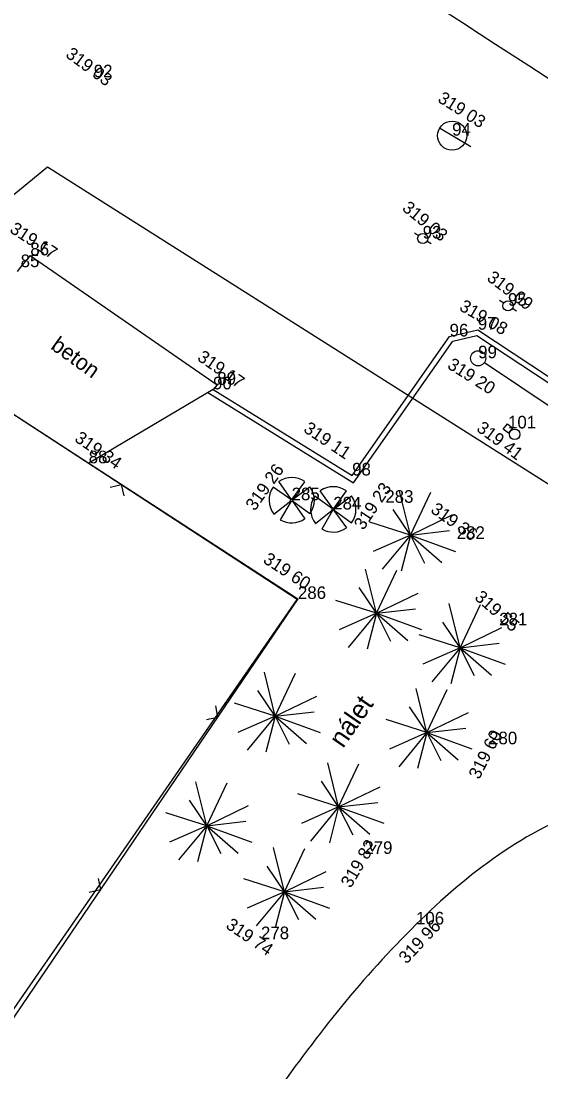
# Model space of a CAD drawing. Extents: x -742884 to -742543, y -1054677 to -1054433.
# Drawn here: x -742659.68 to -742647.31, y -1054548.61 to -1054523.59 of the extents above; entities that cross this region are included whole.
import ezdxf

# ---------------------------------------------------------------- set-up
doc = ezdxf.new("R2010")
doc.units = 0
for name, color, linetype in [('Vrstva 1', 7, 'Continuous'), ('Vrstva 10', 7, 'Continuous'), ('Vrstva 11', 7, 'Continuous'), ('Vrstva 12', 7, 'Continuous'), ('Vrstva 13', 7, 'Continuous'), ('Vrstva 15', 7, 'Continuous'), ('Vrstva 16', 7, 'Continuous'), ('Vrstva 2', 7, 'Continuous'), ('Vrstva 3', 7, 'Continuous'), ('Vrstva 4', 7, 'Continuous'), ('Vrstva 5', 7, 'Continuous'), ('Vrstva 50', 7, 'Continuous'), ('Vrstva 7', 7, 'Continuous'), ('Vrstva 9', 7, 'Continuous')]:
    doc.layers.add(name, color=color, linetype=linetype)

# ---------------------------------------------------------------- blocks, each defined once
blk = doc.blocks.new('Z15')
at = {"layer": 'Vrstva 2'}
for p, q in [((-10, 2), (-8, 6)), ((-10, -2), (-10, 2)), ((-8, 6), (-6, 8)), ((-6, 8), (-2, 10)), ((-2, 10), (2, 10)), ((2, 10), (6, 8)), ((6, 8), (8, 6)), ((8, 6), (10, 2)), ((10, 2), (10, -2)), ((-8, -6), (-10, -2)), ((-6, -8), (-8, -6)), ((-2, -10), (-6, -8)), ((2, -10), (-2, -10)), ((6, -8), (2, -10)), ((8, -6), (6, -8)), ((10, -2), (8, -6))]:
    blk.add_line(p, q, dxfattribs=at)

msp = doc.modelspace()

# ---------------------------------------------------------------- linework, layer by layer
at = {"layer": 'Vrstva 1'}
for p, q in [((-742657.95, -1054524.93), (-742657.95, -1054524.93)), ((-742649.42, -1054526.32), (-742649.42, -1054526.32)), ((-742650.12, -1054528.77), (-742650.12, -1054528.77)), ((-742659.46, -1054529.17), (-742659.46, -1054529.17)), ((-742648.09, -1054530.37), (-742648.09, -1054530.37)), ((-742649.48, -1054531.1), (-742649.48, -1054531.1)), ((-742648.81, -1054530.94), (-742648.81, -1054530.94)), ((-742648.8, -1054531.62), (-742648.8, -1054531.62)), ((-742655.11, -1054532.36), (-742655.11, -1054532.36)), ((-742655.01, -1054532.25), (-742655.01, -1054532.25)), ((-742648.09, -1054533.29), (-742648.09, -1054533.29)), ((-742658.07, -1054534.12), (-742658.07, -1054534.12)), ((-742651.8, -1054534.41), (-742651.8, -1054534.41)), ((-742653.24, -1054535), (-742653.24, -1054535)), ((-742651.01, -1054535.06), (-742651.01, -1054535.06)), ((-742652.25, -1054535.22), (-742652.25, -1054535.22)), ((-742649.31, -1054535.92), (-742649.31, -1054535.92)), ((-742653.09, -1054537.35), (-742653.09, -1054537.35)), ((-742648.3, -1054537.98), (-742648.3, -1054537.98)), ((-742648.54, -1054540.81), (-742648.54, -1054540.81)), ((-742651.51, -1054543.42), (-742651.51, -1054543.42)), ((-742650.28, -1054545.1), (-742650.28, -1054545.1)), ((-742653.97, -1054545.45), (-742653.97, -1054545.45))]:
    msp.add_line(p, q, dxfattribs=at)
at = {"layer": 'Vrstva 10'}
for p, q in [((-742653.252, -1054534.978), (-742653.547, -1054534.555)), ((-742653.224, -1054534.978), (-742652.926, -1054534.558)), ((-742653.261, -1054534.981), (-742653.681, -1054534.686)), ((-742653.22, -1054534.984), (-742652.806, -1054534.678)), ((-742652.262, -1054535.198), (-742652.557, -1054534.775)), ((-742652.234, -1054535.198), (-742651.936, -1054534.778)), ((-742650.412, -1054535.83), (-742650.669, -1054534.78)), ((-742650.412, -1054535.83), (-742649.927, -1054534.805)), ((-742653.261, -1054535.018), (-742653.66, -1054535.338)), ((-742653.255, -1054535.024), (-742653.512, -1054535.465)), ((-742653.223, -1054535.021), (-742652.926, -1054535.439)), ((-742653.216, -1054535.016), (-742652.806, -1054535.319)), ((-742652.271, -1054535.201), (-742652.691, -1054534.906)), ((-742652.23, -1054535.204), (-742651.816, -1054534.898)), ((-742652.271, -1054535.238), (-742652.67, -1054535.558)), ((-742652.265, -1054535.244), (-742652.522, -1054535.685)), ((-742652.233, -1054535.241), (-742651.936, -1054535.659)), ((-742652.226, -1054535.236), (-742651.816, -1054535.539)), ((-742650.412, -1054535.83), (-742650.822, -1054535.219)), ((-742650.412, -1054535.83), (-742649.42, -1054535.351)), ((-742650.412, -1054535.83), (-742651.381, -1054535.523)), ((-742650.412, -1054535.83), (-742651.297, -1054536.223)), ((-742650.412, -1054535.83), (-742651.082, -1054536.644)), ((-742650.412, -1054535.83), (-742650.632, -1054536.689)), ((-742650.416, -1054535.824), (-742650.416, -1054535.824)), ((-742650.412, -1054535.83), (-742649.48, -1054535.724)), ((-742650.412, -1054535.83), (-742650.412, -1054535.83)), ((-742650.412, -1054535.83), (-742650.076, -1054536.494)), ((-742650.412, -1054535.83), (-742649.337, -1054536.219)), ((-742650.412, -1054535.83), (-742649.666, -1054536.483)), ((-742650.412, -1054535.83), (-742650.412, -1054535.83)), ((-742651.222, -1054537.69), (-742651.479, -1054536.64)), ((-742651.222, -1054537.69), (-742650.737, -1054536.665)), ((-742651.222, -1054537.69), (-742651.632, -1054537.079)), ((-742651.222, -1054537.69), (-742650.23, -1054537.211)), ((-742651.222, -1054537.69), (-742652.191, -1054537.383)), ((-742651.222, -1054537.69), (-742650.29, -1054537.584)), ((-742649.232, -1054538.51), (-742649.489, -1054537.46)), ((-742649.232, -1054538.51), (-742648.747, -1054537.485)), ((-742651.222, -1054537.69), (-742652.107, -1054538.083)), ((-742651.222, -1054537.69), (-742651.892, -1054538.504)), ((-742651.222, -1054537.69), (-742651.442, -1054538.549)), ((-742651.226, -1054537.684), (-742651.226, -1054537.684)), ((-742651.222, -1054537.69), (-742651.222, -1054537.69)), ((-742651.222, -1054537.69), (-742650.886, -1054538.354)), ((-742651.222, -1054537.69), (-742650.147, -1054538.079)), ((-742651.222, -1054537.69), (-742650.476, -1054538.343)), ((-742651.222, -1054537.69), (-742651.222, -1054537.69)), ((-742649.232, -1054538.51), (-742649.642, -1054537.899)), ((-742649.232, -1054538.51), (-742648.24, -1054538.031)), ((-742649.232, -1054538.51), (-742650.201, -1054538.203)), ((-742649.232, -1054538.51), (-742650.117, -1054538.903)), ((-742649.232, -1054538.51), (-742649.902, -1054539.324)), ((-742649.232, -1054538.51), (-742649.452, -1054539.369)), ((-742649.236, -1054538.504), (-742649.236, -1054538.504)), ((-742649.232, -1054538.51), (-742648.3, -1054538.404)), ((-742649.232, -1054538.51), (-742649.232, -1054538.51)), ((-742649.232, -1054538.51), (-742648.896, -1054539.174)), ((-742649.232, -1054538.51), (-742648.157, -1054538.899)), ((-742649.232, -1054538.51), (-742648.486, -1054539.163)), ((-742649.232, -1054538.51), (-742649.232, -1054538.51)), ((-742653.632, -1054540.14), (-742653.889, -1054539.09)), ((-742653.632, -1054540.14), (-742653.147, -1054539.115)), ((-742653.632, -1054540.14), (-742654.042, -1054539.529)), ((-742650.022, -1054540.53), (-742650.279, -1054539.48)), ((-742650.022, -1054540.53), (-742649.537, -1054539.505)), ((-742653.632, -1054540.14), (-742654.601, -1054539.833)), ((-742653.632, -1054540.14), (-742652.64, -1054539.661)), ((-742653.632, -1054540.14), (-742652.7, -1054540.034)), ((-742650.022, -1054540.53), (-742650.432, -1054539.919)), ((-742650.022, -1054540.53), (-742649.03, -1054540.051)), ((-742653.632, -1054540.14), (-742654.517, -1054540.533)), ((-742653.632, -1054540.14), (-742654.302, -1054540.954)), ((-742653.632, -1054540.14), (-742653.852, -1054540.999)), ((-742653.636, -1054540.134), (-742653.636, -1054540.134)), ((-742653.632, -1054540.14), (-742653.632, -1054540.14)), ((-742653.632, -1054540.14), (-742653.296, -1054540.804)), ((-742653.632, -1054540.14), (-742652.557, -1054540.529)), ((-742653.632, -1054540.14), (-742652.886, -1054540.793)), ((-742653.632, -1054540.14), (-742653.632, -1054540.14)), ((-742650.022, -1054540.53), (-742650.991, -1054540.223)), ((-742650.022, -1054540.53), (-742650.907, -1054540.923)), ((-742650.022, -1054540.53), (-742650.692, -1054541.344)), ((-742650.022, -1054540.53), (-742650.242, -1054541.389)), ((-742650.026, -1054540.524), (-742650.026, -1054540.524)), ((-742650.022, -1054540.53), (-742649.09, -1054540.424)), ((-742650.022, -1054540.53), (-742650.022, -1054540.53)), ((-742650.022, -1054540.53), (-742649.686, -1054541.194)), ((-742650.022, -1054540.53), (-742648.947, -1054540.919)), ((-742650.022, -1054540.53), (-742649.276, -1054541.183)), ((-742650.022, -1054540.53), (-742650.022, -1054540.53)), ((-742652.122, -1054542.3), (-742652.379, -1054541.25)), ((-742652.122, -1054542.3), (-742651.637, -1054541.275)), ((-742655.262, -1054542.75), (-742655.519, -1054541.7)), ((-742655.262, -1054542.75), (-742654.777, -1054541.725)), ((-742652.122, -1054542.3), (-742652.532, -1054541.689)), ((-742652.122, -1054542.3), (-742651.13, -1054541.821)), ((-742652.122, -1054542.3), (-742653.091, -1054541.993)), ((-742655.262, -1054542.75), (-742655.672, -1054542.139)), ((-742655.262, -1054542.75), (-742654.27, -1054542.271)), ((-742652.122, -1054542.3), (-742653.007, -1054542.693)), ((-742652.122, -1054542.3), (-742652.792, -1054543.114)), ((-742652.122, -1054542.3), (-742652.342, -1054543.159)), ((-742652.126, -1054542.294), (-742652.126, -1054542.294)), ((-742652.122, -1054542.3), (-742651.19, -1054542.194)), ((-742652.122, -1054542.3), (-742652.122, -1054542.3)), ((-742652.122, -1054542.3), (-742651.786, -1054542.964)), ((-742652.122, -1054542.3), (-742651.047, -1054542.689)), ((-742652.122, -1054542.3), (-742651.376, -1054542.953)), ((-742652.122, -1054542.3), (-742652.122, -1054542.3)), ((-742655.262, -1054542.75), (-742656.231, -1054542.443)), ((-742655.262, -1054542.75), (-742656.147, -1054543.143)), ((-742655.262, -1054542.75), (-742655.932, -1054543.564)), ((-742655.262, -1054542.75), (-742655.482, -1054543.609)), ((-742655.266, -1054542.744), (-742655.266, -1054542.744)), ((-742655.262, -1054542.75), (-742654.33, -1054542.644)), ((-742655.262, -1054542.75), (-742655.262, -1054542.75)), ((-742655.262, -1054542.75), (-742654.926, -1054543.414)), ((-742655.262, -1054542.75), (-742654.187, -1054543.139)), ((-742655.262, -1054542.75), (-742654.516, -1054543.403)), ((-742655.262, -1054542.75), (-742655.262, -1054542.75)), ((-742653.412, -1054544.32), (-742653.669, -1054543.27)), ((-742653.412, -1054544.32), (-742652.927, -1054543.295)), ((-742653.412, -1054544.32), (-742653.822, -1054543.709)), ((-742653.412, -1054544.32), (-742652.42, -1054543.841)), ((-742653.412, -1054544.32), (-742654.381, -1054544.013)), ((-742653.412, -1054544.32), (-742654.297, -1054544.713)), ((-742653.412, -1054544.32), (-742654.082, -1054545.134)), ((-742653.412, -1054544.32), (-742653.632, -1054545.179)), ((-742653.416, -1054544.314), (-742653.416, -1054544.314)), ((-742653.412, -1054544.32), (-742652.48, -1054544.214)), ((-742653.412, -1054544.32), (-742653.412, -1054544.32)), ((-742653.412, -1054544.32), (-742653.076, -1054544.984)), ((-742653.412, -1054544.32), (-742652.337, -1054544.709)), ((-742653.412, -1054544.32), (-742652.666, -1054544.973)), ((-742653.412, -1054544.32), (-742653.412, -1054544.32))]:
    msp.add_line(p, q, dxfattribs=at)
for centre, start, end in [((-742653.239, -1054534.998), 54.7465, 124.8105), ((-742653.239, -1054534.997), 144.8767, 218.9336), ((-742653.239, -1054534.998), 323.4756, 36.2971), ((-742652.249, -1054535.218), 54.7465, 124.8105), ((-742652.249, -1054535.217), 144.8767, 218.9336), ((-742652.249, -1054535.218), 323.4756, 36.2971), ((-742653.239, -1054534.998), 239.6151, 305.4552), ((-742652.249, -1054535.218), 239.6151, 305.4552)]:
    msp.add_arc(centre, 0.54, start, end, dxfattribs=at)
at = {"layer": 'Vrstva 11'}
msp.add_spline([(-742641.45, -1054542), (-742646.08, -1054542.32), (-742650.28, -1054545.1), (-742653.63, -1054549.14), (-742658.66, -1054557.13), (-742664.13, -1054565.84), (-742667.81, -1054569.62), (-742669.76, -1054570.07), (-742674.4, -1054567.88), (-742684.66, -1054562.03), (-742693.02, -1054556.88), (-742694.43, -1054554.37), (-742693.99, -1054552.67), (-742684.52, -1054539.64), (-742677.51, -1054529.95), (-742676.26, -1054526.54), (-742677.27, -1054522.39), (-742681.19, -1054517.29), (-742689.28, -1054510.73), (-742697.86, -1054505.14), (-742704.02, -1054502.75), (-742713.11, -1054501.07), (-742723.98, -1054503.51), (-742736.77, -1054510.1), (-742745.39, -1054515.75), (-742752.81, -1054521.82), (-742762.72, -1054531.38), (-742770.54, -1054539.36), (-742775.54, -1054544.64)], degree=3, dxfattribs=at)
at = {"layer": 'Vrstva 12'}
msp.add_lwpolyline([(-742648.65, -1054531.721), (-742646.97, -1054532.848)], dxfattribs=at)
msp.add_circle((-742648.8, -1054531.62), 0.18, dxfattribs=at)
at = {"layer": 'Vrstva 13'}
msp.add_line((-742655.11, -1054532.36), (-742658.07, -1054534.12), dxfattribs=at)
at = {"layer": 'Vrstva 16'}
for p, q in [((-742648.203, -1054533.305), (-742648.1, -1054533.181)), ((-742648.079, -1054533.406), (-742648.203, -1054533.305)), ((-742648.1, -1054533.181), (-742647.977, -1054533.282)), ((-742648.079, -1054533.406), (-742647.977, -1054533.282))]:
    msp.add_line(p, q, dxfattribs=at)
msp.add_circle((-742647.932, -1054533.43), 0.125, dxfattribs=at)
at = {"layer": 'Vrstva 4'}
for p, q in [((-742649.402, -1054531.216), (-742648.833, -1054531.079)), ((-742648.834, -1054531.079), (-742639.248, -1054537.412)), ((-742651.765, -1054534.586), (-742649.402, -1054531.215)), ((-742655.233, -1054532.433), (-742651.765, -1054534.586))]:
    msp.add_line(p, q, dxfattribs=at)
for points in [[(-742659.46, -1054529.17), (-742659.69, -1054529.45), (-742659.773, -1054529.551)], [(-742659.46, -1054529.17), (-742655.01, -1054532.25), (-742655.11, -1054532.36)], [(-742655.11, -1054532.36), (-742651.8, -1054534.41), (-742649.48, -1054531.1), (-742648.81, -1054530.94), (-742639.21, -1054537.28)]]:
    msp.add_lwpolyline(points, dxfattribs=at)
msp.add_spline([(-742718.8, -1054478.84), (-742709.4, -1054484.88), (-742695.99, -1054493.43), (-742680.4, -1054503.55), (-742661.01, -1054516), (-742635.78, -1054532.31)], degree=3, dxfattribs=at)
at = {"layer": 'Vrstva 5'}
for p, q in [((-742657.559, -1054534.689), (-742657.293, -1054534.624)), ((-742657.223, -1054534.892), (-742657.293, -1054534.624)), ((-742653.09, -1054537.35), (-742666.116, -1054556.522)), ((-742655.056, -1054539.894), (-742655.001, -1054540.163)), ((-742655.27, -1054540.223), (-742655.001, -1054540.163)), ((-742657.848, -1054544.002), (-742657.793, -1054544.271)), ((-742658.062, -1054544.331), (-742657.793, -1054544.271))]:
    msp.add_line(p, q, dxfattribs=at)
msp.add_lwpolyline([(-742670.43, -1054526.08), (-742670, -1054526.35), (-742666.49, -1054528.64), (-742661.62, -1054531.81), (-742658.07, -1054534.12), (-742653.09, -1054537.35)], dxfattribs=at)
at = {"layer": 'Vrstva 50'}
for points in [[(-742670.45, -1054526.06), (-742684.78, -1054546.85), (-742687.08, -1054550.18), (-742679.03, -1054555.7), (-742669.36, -1054562.14), (-742666.55, -1054557.95), (-742665.76, -1054556.77), (-742666.29, -1054556.4), (-742653.11, -1054537.36), (-742666.64, -1054528.55)], [(-742666.64, -1054528.55), (-742664.56, -1054529.16), (-742660.48, -1054528.23), (-742659.05, -1054527.06), (-742630.9, -1054544.89), (-742546.289, -1054602.738)]]:
    msp.add_lwpolyline(points, dxfattribs=at)
at = {"layer": 'Vrstva 7'}
msp.add_line((-742648.977, -1054526.584), (-742649.719, -1054526.142), dxfattribs=at)
msp.add_circle((-742649.42, -1054526.32), 0.347, dxfattribs=at)
at = {"layer": 'Vrstva 9'}
for p, q in [((-742650.222, -1054528.705), (-742650.319, -1054528.642)), ((-742649.918, -1054528.899), (-742650.018, -1054528.836)), ((-742648.192, -1054530.305), (-742648.289, -1054530.242)), ((-742647.888, -1054530.499), (-742647.988, -1054530.436))]:
    msp.add_line(p, q, dxfattribs=at)
for centre in [(-742650.12, -1054528.77), (-742648.09, -1054530.37)]:
    msp.add_circle(centre, 0.121, dxfattribs=at)

# ---------------------------------------------------------------- block references
at = {"layer": 'Vrstva 10', "xscale": 0.0026993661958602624, "yscale": 0.002699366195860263, "rotation": -30.671756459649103}
for p in [(-742653.24, -1054535), (-742652.25, -1054535.22)]:
    msp.add_blockref('Z15', p, dxfattribs=at)

# ---------------------------------------------------------------- texts
at = {"layer": 'Vrstva 15'}
for s, height, rotation, p in [('beton', 0.3751, 324.2494, (-742659, -1054531.381)), ('nálet', 0.4497, 55.2544, (-742652.017, -1054540.922))]:
    msp.add_text(s, height=height, rotation=rotation, dxfattribs=at).set_placement(p)
at = {"layer": 'Vrstva 2'}
for s, p in [('92', (-742657.95, -1054524.93)), ('94', (-742649.42, -1054526.32)), ('93', (-742650.12, -1054528.77)), ('86', (-742659.46, -1054529.17)), ('85', (-742659.69, -1054529.45)), ('95', (-742648.09, -1054530.37)), ('96', (-742649.48, -1054531.1)), ('97', (-742648.81, -1054530.94)), ('99', (-742648.8, -1054531.62)), ('90', (-742655.11, -1054532.36)), ('89', (-742655.01, -1054532.25)), ('101', (-742648.09, -1054533.29)), ('88', (-742658.07, -1054534.12)), ('98', (-742651.8, -1054534.41)), ('285', (-742653.24, -1054535)), ('283', (-742651.01, -1054535.06)), ('284', (-742652.25, -1054535.22)), ('282', (-742649.31, -1054535.92)), ('286', (-742653.09, -1054537.35)), ('281', (-742648.3, -1054537.98)), ('280', (-742648.54, -1054540.81)), ('279', (-742651.51, -1054543.42)), ('106', (-742650.28, -1054545.1)), ('278', (-742653.97, -1054545.45))]:
    msp.add_text(s, height=0.3, dxfattribs=at).set_placement(p)
at = {"layer": 'Vrstva 3'}
for s, rotation, p in [('319 03 ', 323.6507, (-742658.641, -1054524.431)), ('319 03 ', 327.8567, (-742649.784, -1054525.501)), ('319 03 ', 320.7391, (-742650.63, -1054528.081)), ('319 17 ', 327.038, (-742659.971, -1054528.606)), ('319 09 ', 322.7403, (-742648.614, -1054529.749)), ('319 08 ', 329.6067, (-742649.271, -1054530.461)), ('319 17 ', 325.2938, (-742655.506, -1054531.652)), ('319 20 ', 327.8288, (-742649.555, -1054531.843)), ('319 11 ', 326.2034, (-742652.978, -1054533.356)), ('319 41 ', 323.5691, (-742648.86, -1054533.334)), ('319 34 ', 325.2893, (-742658.427, -1054533.58)), ('319 26 ', 54.5716, (-742654.118, -1054535.272)), ('319 23 ', 56.3099, (-742651.531, -1054535.728)), ('319 36 ', 324.4941, (-742649.952, -1054535.273)), ('319 60 ', 326.8161, (-742653.941, -1054536.471)), ('319 55 ', 318.6173, (-742648.905, -1054537.341)), ('319 60 ', 63.2129, (-742648.777, -1054541.663)), ('319 82 ', 59.2373, (-742651.834, -1054544.25)), ('319 74 ', 325.8301, (-742654.828, -1054545.171)), ('319 96 ', 46.8695, (-742650.506, -1054546.056))]:
    msp.add_text(s, height=0.3, rotation=rotation, dxfattribs=at).set_placement(p)

doc.saveas('drawing.dxf')
